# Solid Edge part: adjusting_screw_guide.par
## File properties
Title: Adjusting screw guide
Author: Deepak Maini
Template: Normal.par
Last saved by: Robert a Rhodes jr
Revision: 2
Application: Solid Edge
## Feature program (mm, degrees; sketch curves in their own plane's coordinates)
sketch for "unnamed Protrusion 1" plane through (0, 0, 0) normal (0, -1, 0) x-axis (1, 0, 0)
  circle centre (0, 0) radius 7.9375
extrude "unnamed Protrusion 1" add finite 63.5 along +normal
sketch for "unnamed Protrusion 2" plane through (0, -63.5, 0) normal (0, -1, 0) x-axis (1, 0, 0)
  circle centre (0, 0) radius 6.3119
extrude "unnamed Protrusion 2" add finite 76.2 along +normal
chamfer "unnamed Chamfer 1"
sketch for "unnamed Cutout 1" plane through (0, 0, 0) normal (0, 0, 1) x-axis (1, 0, 0)
  line (1.1811, 0) -> (1.1811, -4.7498)
  line (1.1811, -4.7498) -> (-1.1811, -4.7498)
  line (-1.1811, -4.7498) -> (-1.1811, 0)
  line (-1.1811, 0) -> (1.1811, 0)
extrude "unnamed Cutout 1" cut finite 101.6 symmetric
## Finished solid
Body 1: solid body, 10 faces, 16 edges, 8 vertices.
  Faces by surface: plane 7, cylinder 2, cone 1
  Edges by curve: circle 8, line 8
Bounding box of the edges (mm): 15.875 x 139.700 x 15.875, from (-7.9375, -139.7, -7.9375) to (7.9375, 0, 7.9375).
Cylindrical faces by radius (mm): R6.3119 x1, R7.9375 x1
Conical faces (half-angle, radius in mm at the cone's reference point): 45 deg R6.3119 x1
Planar faces by outward normal: +x 1, +y 3, -x 1, -y 2
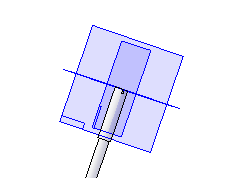
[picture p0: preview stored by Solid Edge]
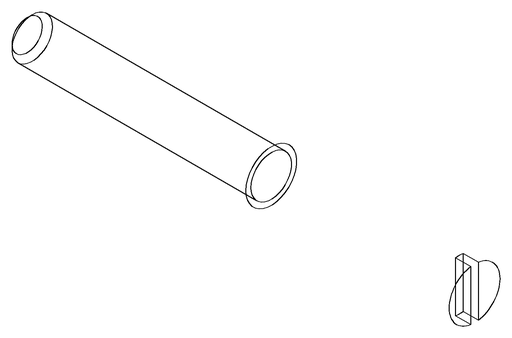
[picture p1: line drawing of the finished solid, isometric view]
